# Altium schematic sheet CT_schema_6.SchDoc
size 479 x 328 mm
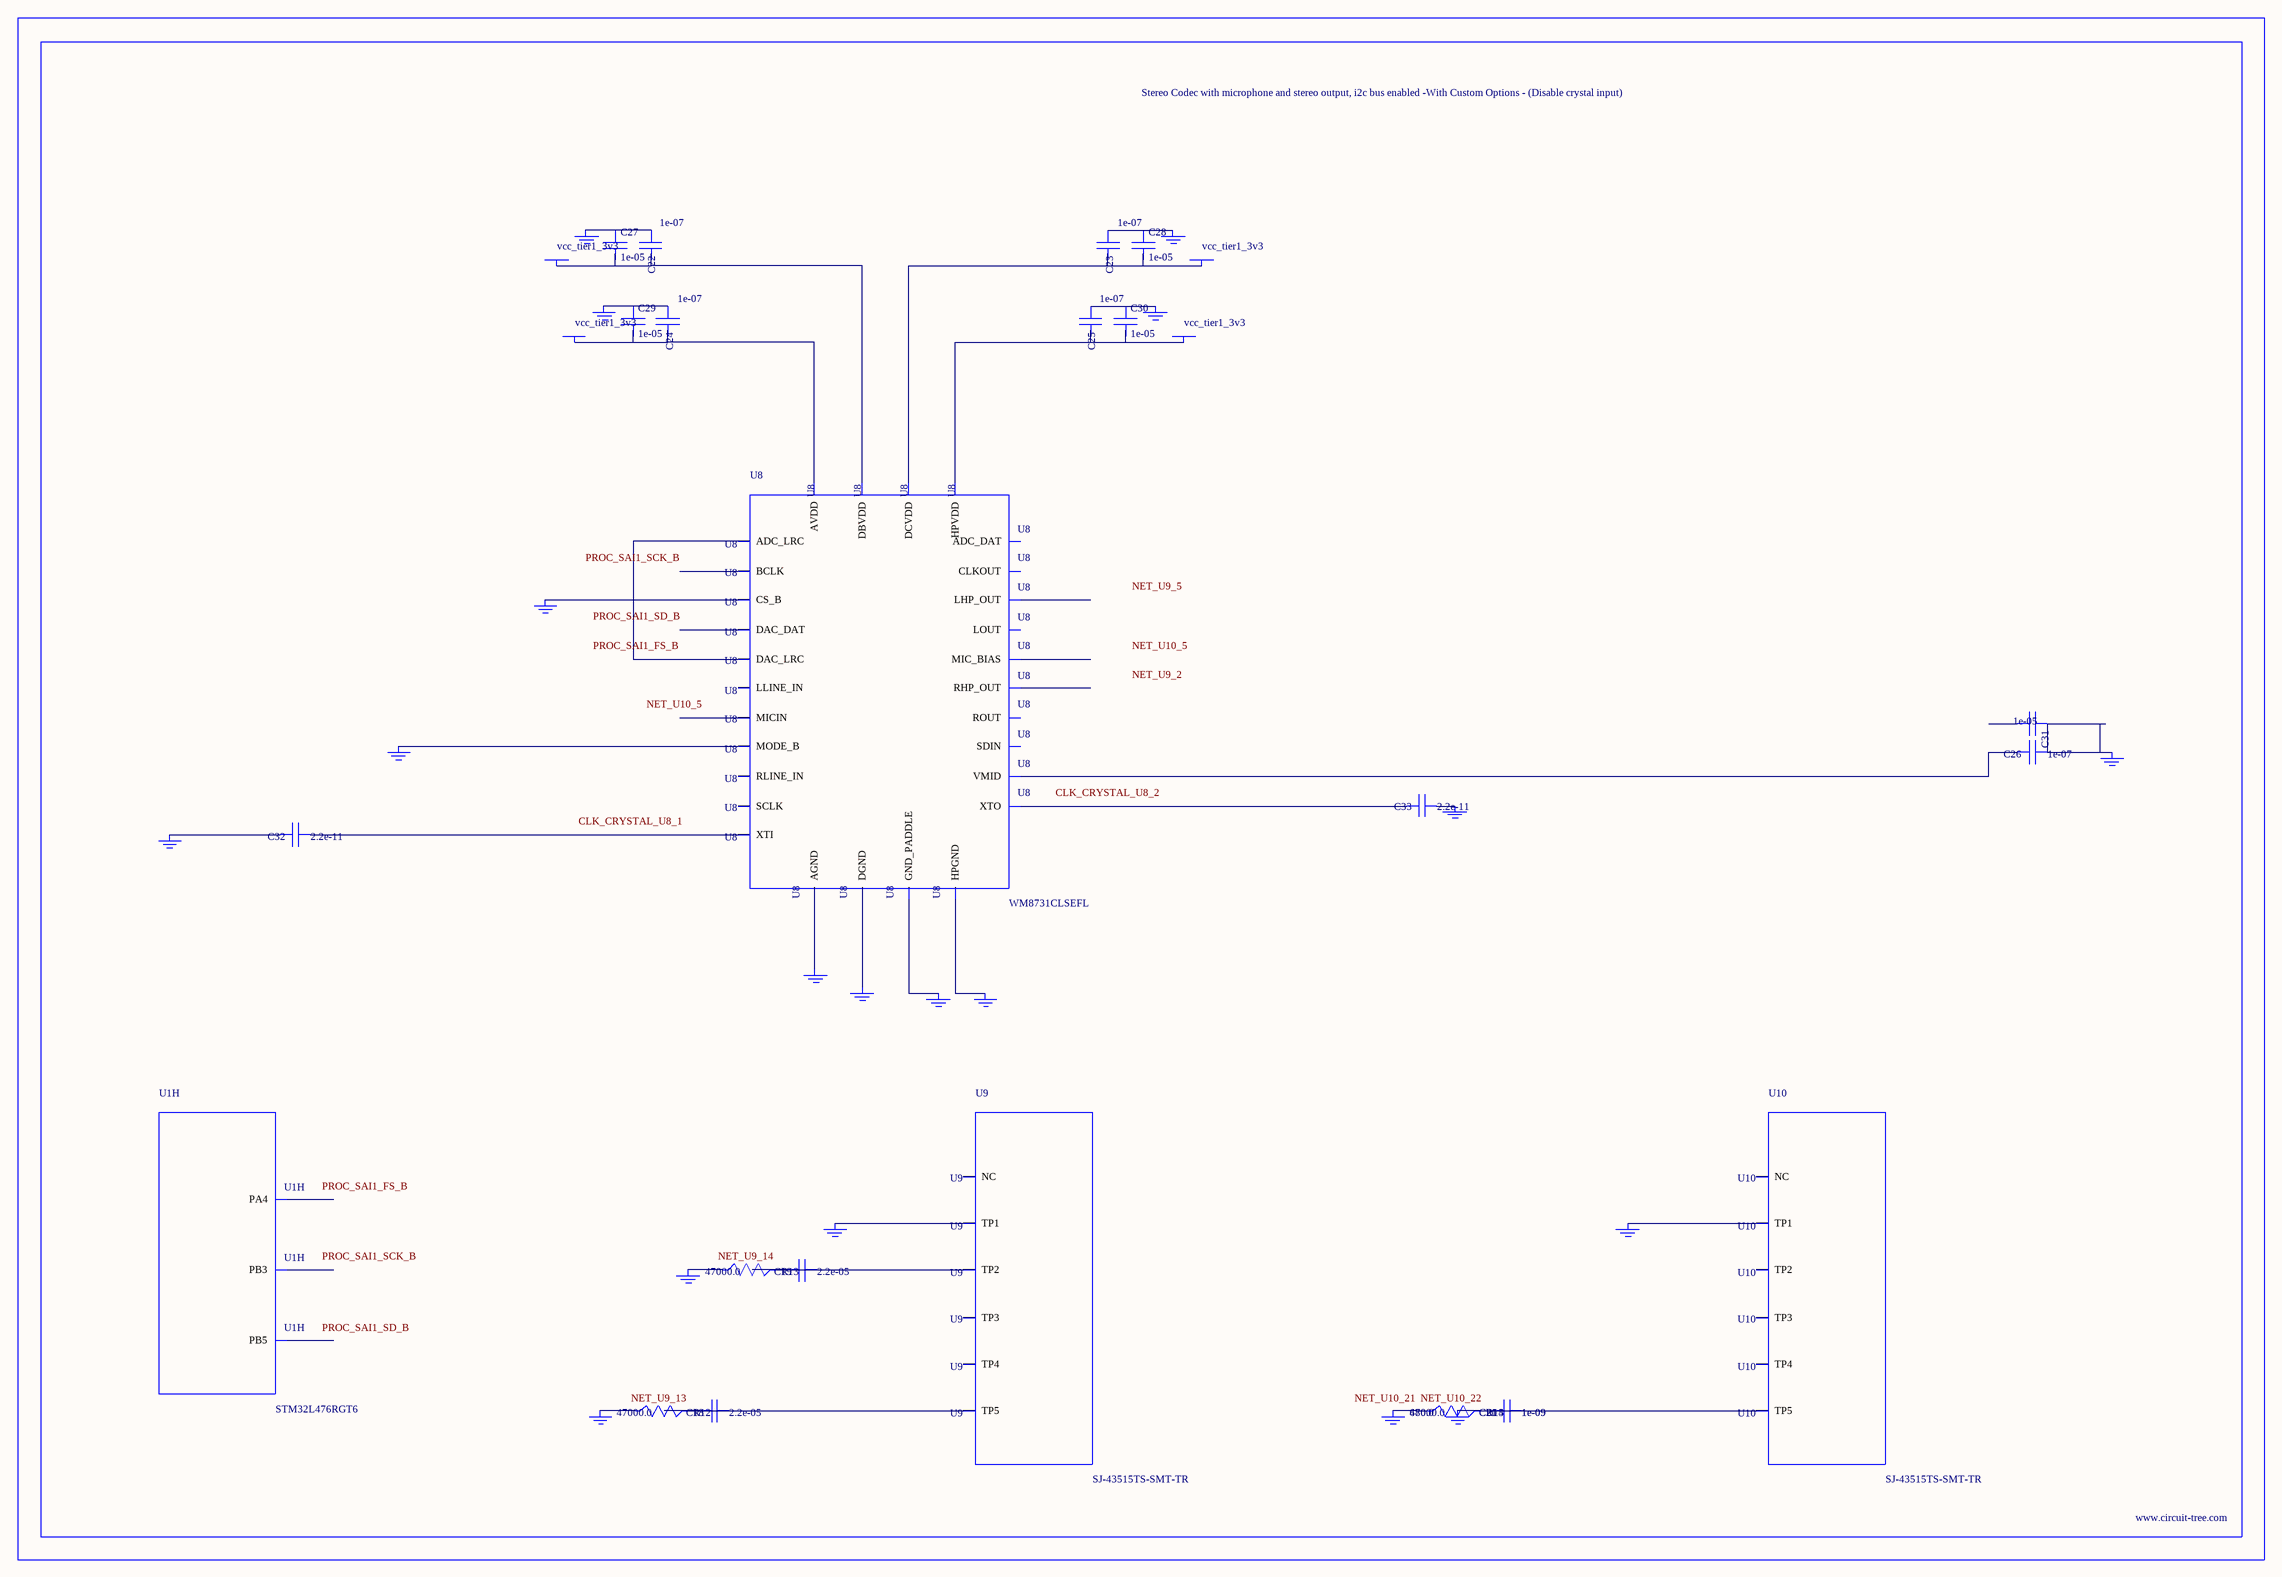
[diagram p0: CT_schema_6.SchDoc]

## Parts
BORDER5  (no value)
C18  2.2e-05  [C1210]
C19  2.2e-05  [C1210]
C20  1e-09  [C0402]
C21  1e-09  [C0402]
C22  1e-07  [C0402]
C23  1e-07  [C0402]
C24  1e-07  [C0402]
C25  1e-07  [C0402]
C26  1e-07  [C0402]
C27  1e-05  [C0805]
C28  1e-05  [C0805]
C29  1e-05  [C0805]
C30  1e-05  [C0805]
C31  1e-05  [C0805]
C32  2.2e-11  [C0402]
C33  2.2e-11  [C0402]
GND_INSTANCE_5_0  (no value)
GND_INSTANCE_5_1  (no value)
GND_INSTANCE_5_2  (no value)
GND_INSTANCE_5_3  (no value)
GND_INSTANCE_5_4  (no value)
GND_INSTANCE_5_5  (no value)
GND_INSTANCE_5_6  (no value)
GND_INSTANCE_5_7  (no value)
GND_INSTANCE_5_8  (no value)
GND_INSTANCE_5_9  (no value)
GND_INSTANCE_5_10  (no value)
GND_INSTANCE_5_11  (no value)
GND_INSTANCE_5_12  (no value)
GND_INSTANCE_5_13  (no value)
GND_INSTANCE_5_14  (no value)
GND_INSTANCE_5_15  (no value)
GND_INSTANCE_5_16  (no value)
GND_INSTANCE_5_17  (no value)
GND_INSTANCE_5_18  (no value)
POWER_INSTANCE_5_0  vcc_tier1_3v3
POWER_INSTANCE_5_1  vcc_tier1_3v3
POWER_INSTANCE_5_2  vcc_tier1_3v3
POWER_INSTANCE_5_3  vcc_tier1_3v3
R12  47000.0  [R0603]
R13  47000.0  [R0603]
R14  47000.0  [R0603]
R15  680.0  [R0603]
U1  STM32L476RGT6  [LQFP64]  (part H of 8)
U8  WM8731CLSEFL  [QFN-28]
U9  SJ-43515TS-SMT-TR  [SJ-43515TS-SMT-TR]
U10  SJ-43515TS-SMT-TR  [SJ-43515TS-SMT-TR]

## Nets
NetC18_1: C18.1 C18.2 R12.2 U9.5(TP5)
NetC19_1: C19.1 C19.2 R13.2 U9.2(TP2)
NetC20_1: C20.1 C20.2 C21.1 C21.2 GND_INSTANCE_5_18.0(GND) R14.2 R15.2 U10.5(TP5)
NetC22_1: C22.1 C27.1 GND_INSTANCE_5_3.0(GND)
NetC22_2: C22.2 C27.2 POWER_INSTANCE_5_1.0(PWR) U8.5(DBVDD)
NetC23_1: C23.1 C28.1 GND_INSTANCE_5_2.0(GND)
NetC23_2: C23.2 C28.2 POWER_INSTANCE_5_0.0(PWR) U8.3(DCVDD)
NetC24_1: C24.1 C29.1 GND_INSTANCE_5_6.0(GND)
NetC24_2: C24.2 C29.2 POWER_INSTANCE_5_3.0(PWR) U8.18(AVDD)
NetC25_1: C25.1 C30.1 GND_INSTANCE_5_4.0(GND)
NetC25_2: C25.2 C30.2 POWER_INSTANCE_5_2.0(PWR) U8.12(HPVDD)
NetC26_1: C26.1 C31.1 GND_INSTANCE_5_7.0(GND)
NetC26_2: C26.2 U8.20(VMID)
NetC32_1: C32.1 U8.1(XTI)
NetC32_2: C32.2 GND_INSTANCE_5_0.0(GND)
NetC33_1: C33.1 GND_INSTANCE_5_1.0(GND)
NetC33_2: C33.2 U8.2(XTO)
NetGND_INSTANCE_5_5_0: GND_INSTANCE_5_5.0(GND) U8.15(HPGND)
NetGND_INSTANCE_5_8_0: GND_INSTANCE_5_8.0(GND) U8.25(MODE_B)
NetGND_INSTANCE_5_9_0: GND_INSTANCE_5_9.0(GND) U8.26(CS_B)
NetGND_INSTANCE_5_10_0: GND_INSTANCE_5_10.0(GND) U8.29(GND_PADDLE)
NetGND_INSTANCE_5_11_0: GND_INSTANCE_5_11.0(GND) U8.4(DGND)
NetGND_INSTANCE_5_12_0: GND_INSTANCE_5_12.0(GND) U8.19(AGND)
NetGND_INSTANCE_5_13_0: GND_INSTANCE_5_13.0(GND) U9.1(TP1)
NetGND_INSTANCE_5_14_0: GND_INSTANCE_5_14.0(GND) R13.1
NetGND_INSTANCE_5_15_0: GND_INSTANCE_5_15.0(GND) R12.1
NetGND_INSTANCE_5_16_0: GND_INSTANCE_5_16.0(GND) U10.1(TP1)
NetGND_INSTANCE_5_17_0: GND_INSTANCE_5_17.0(GND) R14.1 R15.1
NetU8_9: U8.9(DAC_LRC) U8.11(ADC_LRC)

Not connected (* = marked no-connect by the designer): C31 2; U1 20(PA4) 55(PB3) 57(PB5); U8 6(CLKOUT) 7(BCLK) 8(DAC_DAT) 10(ADC_DAT) 13(LHP_OUT) 14(RHP_OUT) 16(LOUT) 17(ROUT) 21(MIC_BIAS) 22(MICIN) 23(RLINE_IN) 24(LLINE_IN) 27(SDIN) 28(SCLK); U9 3(TP3) 4(TP4) 6(NC); U10 2(TP2) 3(TP3) 4(TP4) 6(NC)

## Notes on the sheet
- Labels drawn without touching a wire or pin: CLK_CRYSTAL_U8_1, CLK_CRYSTAL_U8_2, NET_U9_2, NET_U9_5, NET_U9_13, NET_U9_14, NET_U10_5, NET_U10_21, NET_U10_22, PROC_SAI1_FS_B, PROC_SAI1_SCK_B, PROC_SAI1_SD_B

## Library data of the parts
BORDER5 = BORDER_PAGE5
C18 C19 = C1210C224K5RACTU
C20 C21 = C0402C102K3RAC
C22-C26 = C0402C104K3RACTU
C27-C31 = C0805C106K8RACTU
C32 C33 = C0402C220K3RAC
GND_INSTANCE_5_0-GND_INSTANCE_5_18 = GND
POWER_INSTANCE_5_0-POWER_INSTANCE_5_3 = PWR
R12-R14 = RC0603JR-0747KL
R15 = RC0603JR-07680RL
